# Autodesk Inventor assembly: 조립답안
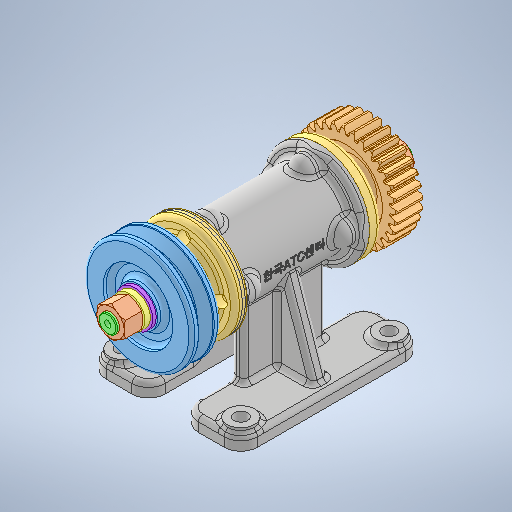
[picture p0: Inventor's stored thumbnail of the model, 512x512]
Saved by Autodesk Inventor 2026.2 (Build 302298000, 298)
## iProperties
Created: 2026-06
Part Number: 조립답안
Document SubType Name: Weldment
Designer: sec7
Weld Material: Welded Aluminum-6061
Author: sec7
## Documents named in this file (13)
- C:\Users\sec7\Desktop\ATC이미희\조립답안.iam
- C:\Users\sec7\Desktop\ATC이미희\본체.ipt
- C:\Users\sec7\Desktop\ATC이미희\6각 너트 M12x1.ipt
- C:\Users\sec7\Desktop\ATC이미희\V 벨트 풀리.ipt
- C:\Users\sec7\Desktop\ATC이미희\깊은 홈 볼 베어링 6904.ipt
- C:\Users\sec7\Desktop\ATC이미희\스퍼 기어.ipt
- C:\Users\sec7\Desktop\ATC이미희\스프링 와셔 M12.ipt
- C:\Users\sec7\Desktop\ATC이미희\오일 실 20 35 8.ipt
- C:\Users\sec7\Desktop\ATC이미희\축.ipt
- C:\Users\sec7\Desktop\ATC이미희\커버.ipt
- C:\Users\sec7\Desktop\ATC이미희\평행 키 4x4x14.ipt
- C:\Users\sec7\Desktop\ATC이미희\평 와셔 M12.ipt
- C:\Users\sec7\Desktop\ATC이미희\6각 구멍붙이 볼트 M4x8.ipt
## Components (7 placed, 3 different names)
1. 6각 너트 M12x1:1
2. V 벨트 풀리:1
3. 6각 너트 M12x1:2
4. 6각 구멍붙이 볼트 M4x8:1
5. 6각 구멍붙이 볼트 M4x8:2
6. 6각 구멍붙이 볼트 M4x8:3
7. 6각 구멍붙이 볼트 M4x8:4
